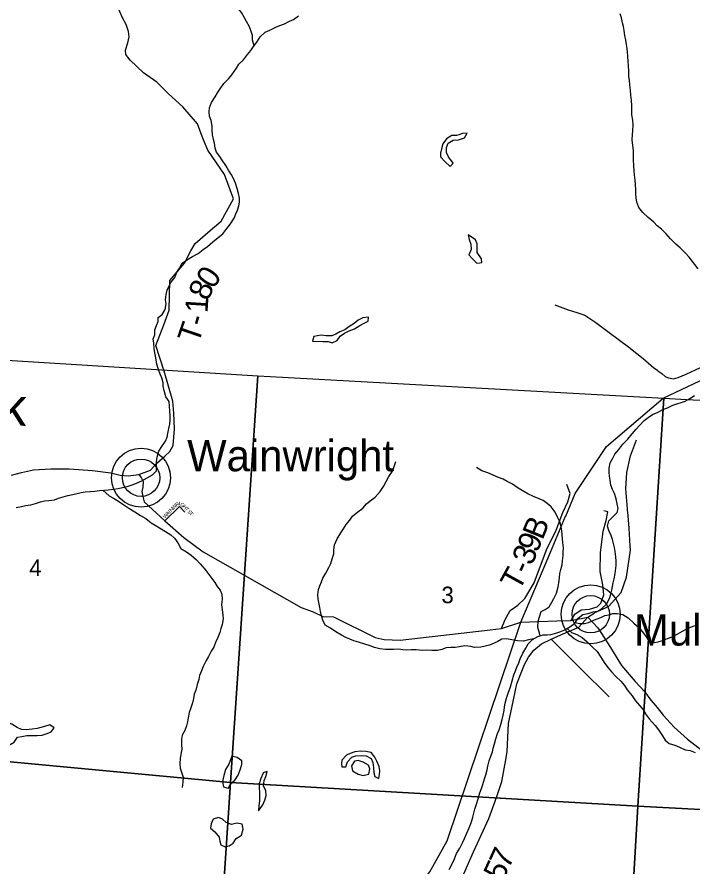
# Model space of a CAD drawing. Extents: x 1715311 to 2083412, y 146837 to 553079.
# Drawn here: x 1969763 to 1978768, y 403543 to 414870 of the extents above; entities that cross this region are included whole.
import ezdxf

# ---------------------------------------------------------------- set-up
doc = ezdxf.new("R2010")
doc.units = 0
for name, color, linetype in [('GM_X_County_Road', 7, 'Continuous'), ('GM_X_Major_River_Text', 7, 'Continuous'), ('GM_X_Minor_Lake', 7, 'Continuous'), ('GM_X_Minor_River', 7, 'Continuous'), ('GM_X_Section', 7, 'Continuous'), ('GM_X_Section_Text', 7, 'Continuous'), ('GM_X_State_Route', 7, 'Continuous'), ('GM_X_Township_Road', 7, 'Continuous'), ('GM_X_Township_Road_Text', 7, 'Continuous'), ('GM_X_Township_ROW', 7, 'Continuous'), ('GM_X_Township_Subdivision', 7, 'Continuous'), ('GM_X_Township_Subdivision_Text', 7, 'Continuous'), ('GM_X_Unincorporated', 7, 'Continuous'), ('GM_X_Unincorporated_Location', 7, 'Continuous'), ('GM_X_Unincorporated_Text', 7, 'Continuous')]:
    doc.layers.add(name, color=color, linetype=linetype)

msp = doc.modelspace()

# ---------------------------------------------------------------- linework, layer by layer
at = {"layer": 'GM_X_County_Road'}
for points in [[(1969690, 408766), (1969822, 408801), (1969984, 408834), (1970214, 408850), (1970458, 408849), (1970769, 408826), (1971014, 408794), (1971138, 408763), (1971244, 408756), (1971384, 408773), (1971419, 408733), (1971445, 408681), (1971440, 408605), (1971426, 408547), (1971437, 408481), (1971455, 408409), (1971733, 408154), (1971984, 407934), (1972245, 407742), (1973547, 407002), (1973710, 406945), (1973836, 406881), (1973977, 406876), (1974536, 406600), (1974656, 406575), (1974868, 406567), (1976068, 406704)], [(1976068, 406704), (1976215, 406720), (1976476, 406805), (1976952, 406822), (1976954, 406822)], [(1976954, 406822), (1977145, 406829), (1977161, 406830), (1977367, 406873), (1977498, 406731), (1977669, 406468), (1977817, 406228), (1977999, 406015), (1978120, 405880), (1978208, 405767), (1978209, 405766)], [(1978209, 405766), (1978211, 405763), (1978292, 405668), (1978369, 405568), (1978518, 405404), (1978696, 405247), (1978891, 405095), (1979079, 404890), (1979255, 404702), (1979433, 404391), (1979537, 404242), (1979659, 403933), (1979721, 403720), (1979743, 403581), (1979744, 403576)]]:
    msp.add_lwpolyline(points, dxfattribs=at)
at = {"layer": 'GM_X_Minor_Lake'}
for points in [[(1975647, 413301), (1975616, 413289), (1975556, 413291), (1975486, 413247), (1975436, 413179), (1975416, 413113), (1975404, 413055), (1975404, 413005), (1975462, 412943), (1975534, 412879)], [(1975534, 412879), (1975571, 412924), (1975510, 413007), (1975484, 413065), (1975486, 413133), (1975506, 413187), (1975572, 413227), (1975646, 413233), (1975722, 413261), (1975760, 413323), (1975696, 413319), (1975647, 413301)], [(1975772, 411969), (1975784, 411905), (1975808, 411843), (1975812, 411774), (1975780, 411702), (1975830, 411646), (1975887, 411588), (1975927, 411594)], [(1975927, 411594), (1975953, 411598), (1975951, 411648), (1975891, 411730), (1975891, 411849), (1975869, 411899), (1975772, 411969)], [(1974414, 410805), (1974439, 410816), (1974445, 410868), (1974371, 410862), (1974307, 410828), (1974255, 410786), (1974183, 410740), (1974131, 410702), (1974062, 410674), (1974010, 410642), (1973958, 410622), (1973880, 410622), (1973816, 410630), (1973718, 410614)], [(1973718, 410614), (1973698, 410552), (1973838, 410544), (1973908, 410546), (1973960, 410530), (1974028, 410560), (1974066, 410616), (1974127, 410656), (1974189, 410686), (1974259, 410714), (1974331, 410758), (1974387, 410792), (1974414, 410805)], [(1969295, 405416), (1969269, 405344), (1969233, 405288), (1969264, 405236), (1969330, 405258), (1969397, 405288), (1969452, 405281), (1969530, 405215), (1969582, 405177), (1969674, 405173), (1969726, 405205), (1969768, 405273), (1969828, 405280), (1969894, 405294), (1969956, 405294), (1970030, 405296), (1970096, 405298), (1970167, 405323)], [(1970167, 405323), (1970220, 405343), (1970260, 405399), (1970199, 405439), (1970131, 405416), (1970080, 405400), (1970030, 405390), (1969963, 405380), (1969885, 405370), (1969823, 405374), (1969765, 405403), (1969695, 405447), (1969625, 405473), (1969555, 405461), (1969479, 405426), (1969417, 405408), (1969365, 405416), (1969295, 405416)], [(1974565, 404730), (1974582, 404722), (1974592, 404774), (1974594, 404824), (1974588, 404884), (1974558, 404954), (1974529, 405008), (1974479, 405067), (1974411, 405083), (1974337, 405087), (1974265, 405077), (1974201, 405057), (1974151, 405034), (1974091, 404968), (1974085, 404918)], [(1972626, 405018), (1972583, 404914), (1972539, 404842), (1972519, 404764), (1972499, 404682), (1972513, 404612), (1972560, 404598)], [(1972560, 404598), (1972580, 404592), (1972609, 404650), (1972663, 404700), (1972709, 404766), (1972737, 404838), (1972757, 404908), (1972756, 404958), (1972694, 405004), (1972626, 405018)], [(1974085, 404918), (1974088, 404878), (1974142, 404879), (1974165, 404945), (1974221, 405005), (1974277, 405023), (1974357, 405029), (1974415, 405023), (1974479, 404987), (1974502, 404934), (1974512, 404864), (1974516, 404798), (1974528, 404748), (1974565, 404730)], [(1974426, 404777), (1974448, 404782), (1974464, 404851), (1974444, 404901), (1974373, 404941), (1974309, 404963), (1974259, 404951)], [(1974259, 404951), (1974218, 404889), (1974234, 404825), (1974306, 404781), (1974376, 404763), (1974426, 404777)], [(1972979, 404290), (1973039, 404372), (1973064, 404434), (1973084, 404494), (1973076, 404558), (1973046, 404626), (1973057, 404696), (1973079, 404750), (1973097, 404814), (1973057, 404800)], [(1973057, 404800), (1973043, 404795), (1973013, 404721), (1972988, 404651), (1972988, 404601), (1972992, 404529), (1972992, 404474), (1972992, 404424), (1972983, 404360), (1972979, 404290)], [(1972375, 404182), (1972351, 404116), (1972341, 404060), (1972397, 404010), (1972456, 403942), (1972466, 403888), (1972480, 403837), (1972534, 403813), (1972590, 403825), (1972642, 403861), (1972682, 403921), (1972727, 403950)], [(1972727, 403950), (1972754, 403969), (1972777, 404049), (1972763, 404115), (1972693, 404125), (1972621, 404111), (1972551, 404137), (1972499, 404178), (1972445, 404202), (1972375, 404182)]]:
    msp.add_lwpolyline(points, dxfattribs=at)
at = {"layer": 'GM_X_Minor_River'}
for points in [[(1972921, 414488), (1972902, 414561), (1972900, 414625), (1972880, 414691), (1972860, 414741), (1972820, 414811), (1972792, 414861), (1972752, 414929), (1972714, 414981), (1972680, 415031), (1972640, 415081), (1972594, 415159), (1972552, 415231), (1972498, 415295), (1972441, 415339), (1972393, 415369)], [(1971788, 409745), (1971745, 409809), (1971723, 409891), (1971711, 409947), (1971709, 409997), (1971693, 410061), (1971671, 410112), (1971649, 410174), (1971627, 410244), (1971611, 410330), (1971601, 410396), (1971591, 410452), (1971585, 410522), (1971577, 410582), (1971597, 410636), (1971599, 410702), (1971619, 410760), (1971643, 410812), (1971645, 410864), (1971697, 410906), (1971737, 410974), (1971749, 411048), (1971743, 411102), (1971751, 411174), (1971762, 411228), (1971786, 411280), (1971814, 411330), (1971864, 411400), (1971892, 411468), (1971926, 411522), (1971964, 411588), (1972032, 411640), (1972102, 411680), (1972176, 411720), (1972243, 411770), (1972301, 411814), (1972371, 411876), (1972443, 411932), (1972505, 411982), (1972543, 412032), (1972607, 412112), (1972654, 412190), (1972680, 412246), (1972700, 412296), (1972716, 412354), (1972726, 412404), (1972726, 412458), (1972714, 412516), (1972694, 412584), (1972672, 412654), (1972646, 412716), (1972622, 412769), (1972581, 412829), (1972543, 412893), (1972497, 412961), (1972465, 413011), (1972421, 413069), (1972403, 413121), (1972393, 413187), (1972381, 413237), (1972367, 413301), (1972363, 413365), (1972363, 413415), (1972351, 413489), (1972329, 413547), (1972321, 413605), (1972327, 413661), (1972355, 413731), (1972401, 413807), (1972433, 413859), (1972469, 413913), (1972517, 413983), (1972584, 414051), (1972626, 414101), (1972688, 414189), (1972716, 414241), (1972782, 414301), (1972834, 414371), (1972880, 414425), (1972912, 414475), (1972956, 414537), (1973001, 414607), (1973069, 414669), (1973131, 414697), (1973211, 414735), (1973265, 414755), (1973325, 414779), (1973395, 414813), (1973448, 414839), (1973514, 414887)], [(1978837, 411515), (1978717, 411671), (1978667, 411723), (1978596, 411793), (1978540, 411841), (1978468, 411913), (1978404, 411983), (1978348, 412045), (1978290, 412087), (1978246, 412137), (1978170, 412199), (1978101, 412263), (1978047, 412333), (1978021, 412403), (1978009, 412459), (1978005, 412511), (1978005, 412567), (1978003, 412637), (1977997, 412697), (1977989, 412767), (1977983, 412819), (1977979, 412887), (1977977, 412969), (1977973, 413023), (1977973, 413091), (1977965, 413159), (1977959, 413233), (1977961, 413303), (1977965, 413353), (1977971, 413433), (1977967, 413497), (1977955, 413565), (1977955, 413691), (1977949, 413759), (1977941, 413829), (1977933, 413897), (1977925, 413967), (1977921, 414027), (1977915, 414079), (1977911, 414146), (1977907, 414222), (1977905, 414278), (1977901, 414348), (1977895, 414402), (1977891, 414452), (1977881, 414506), (1977871, 414562), (1977861, 414624), (1977853, 414692), (1977843, 414742), (1977829, 414792), (1977815, 414860), (1977799, 414912)], [(1969754, 408333), (1969822, 408347), (1969876, 408361), (1969946, 408371), (1970008, 408386), (1970078, 408408), (1970128, 408422), (1970186, 408428), (1970262, 408438), (1970314, 408456), (1970378, 408477), (1970440, 408493), (1970508, 408507), (1970564, 408521), (1970616, 408533), (1970672, 408541), (1970738, 408548), (1970800, 408552), (1970862, 408560), (1970924, 408566), (1970978, 408568), (1971042, 408578), (1971110, 408587), (1971168, 408599), (1971230, 408615), (1971296, 408637), (1971356, 408659), (1971428, 408691), (1971498, 408730), (1971566, 408770), (1971622, 408822), (1971621, 408890), (1971619, 408940), (1971629, 409006), (1971653, 409084), (1971693, 409146), (1971740, 409216), (1971764, 409270), (1971770, 409320), (1971786, 409388), (1971800, 409444), (1971802, 409494), (1971803, 409550), (1971799, 409622), (1971788, 409745)], [(1976423, 406208), (1976447, 406262), (1976466, 406318), (1976502, 406394), (1976542, 406460), (1976572, 406518), (1976630, 406574), (1976700, 406615), (1976772, 406637), (1976824, 406635), (1976876, 406639), (1976942, 406657), (1976994, 406677), (1977062, 406702), (1977125, 406744), (1977193, 406792), (1977239, 406860), (1977301, 406906), (1977371, 406920), (1977437, 406942), (1977499, 406953), (1977553, 406989), (1977615, 407045), (1977657, 407123), (1977674, 407177), (1977686, 407231), (1977694, 407281), (1977704, 407331), (1977716, 407381), (1977730, 407453), (1977743, 407561), (1977743, 407619), (1977741, 407675), (1977729, 407749), (1977722, 407800), (1977710, 407854), (1977696, 407906), (1977678, 407960), (1977648, 408026), (1977631, 408086), (1977645, 408158), (1977705, 408212), (1977759, 408268), (1977771, 408320), (1977757, 408384), (1977746, 408450), (1977724, 408518), (1977694, 408574), (1977674, 408630), (1977664, 408696), (1977655, 408751), (1977649, 408805), (1977651, 408859), (1977665, 408927), (1977699, 408991), (1977725, 409043), (1977778, 409106), (1977834, 409178), (1977898, 409244), (1977956, 409314), (1978010, 409376), (1978053, 409428), (1978117, 409494), (1978187, 409546), (1978237, 409578), (1978295, 409601), (1978367, 409641), (1978429, 409663), (1978497, 409699), (1978664, 409750)], [(1978664, 409750), (1978724, 409788), (1978789, 409826)], [(1976644, 406582), (1976578, 406572), (1976510, 406554), (1976432, 406558), (1976356, 406572), (1976285, 406585), (1976221, 406579), (1976169, 406549), (1976118, 406525), (1976058, 406499), (1976000, 406485), (1975940, 406474), (1975858, 406470), (1975807, 406482), (1975729, 406490), (1975659, 406476), (1975601, 406469), (1975543, 406469), (1975479, 406463), (1975423, 406441), (1975363, 406429), (1975291, 406427), (1975217, 406432), (1975161, 406428), (1975081, 406436), (1975017, 406436), (1974957, 406434), (1974901, 406439), (1974849, 406447), (1974777, 406443), (1974723, 406441), (1974671, 406443), (1974597, 406451), (1974527, 406470), (1974467, 406490), (1974397, 406512), (1974312, 406540), (1974252, 406555), (1974196, 406577), (1974144, 406601), (1974084, 406633), (1974008, 406675), (1973938, 406724), (1973867, 406766), (1973835, 406830), (1973821, 406888), (1973807, 406948), (1973795, 407002), (1973782, 407066), (1973774, 407116), (1973772, 407170), (1973780, 407239), (1973796, 407291), (1973818, 407342), (1973835, 407394), (1973877, 407460), (1973917, 407532), (1973943, 407586), (1973963, 407650), (1973982, 407714), (1973982, 407768), (1973994, 407838), (1974026, 407918), (1974078, 407996), (1974110, 408048), (1974147, 408108), (1974195, 408164), (1974233, 408216), (1974301, 408278), (1974371, 408324), (1974417, 408384), (1974467, 408422), (1974534, 408473), (1974602, 408545), (1974646, 408613), (1974680, 408679), (1974718, 408747), (1974765, 408819), (1974785, 408881), (1974811, 408947)], [(1976731, 406625), (1976721, 406661), (1976701, 406736), (1976705, 406820), (1976721, 406876), (1976745, 406946), (1976797, 406974), (1976852, 407011), (1976886, 407071), (1976914, 407123), (1976950, 407193), (1976970, 407275), (1976981, 407329), (1976989, 407395), (1976993, 407455), (1977007, 407507), (1977023, 407569), (1977031, 407623), (1977038, 407693), (1977040, 407743), (1977042, 407795), (1977036, 407866), (1977028, 407916), (1977025, 407972), (1977021, 408022), (1977011, 408074), (1976995, 408142), (1976969, 408194), (1976930, 408270), (1976878, 408342), (1976826, 408385), (1976772, 408425), (1976720, 408451), (1976644, 408481), (1976567, 408517), (1976491, 408560), (1976439, 408592), (1976363, 408646), (1976293, 408682), (1976241, 408709), (1976175, 408733), (1976106, 408765), (1976034, 408797), (1975956, 408824), (1975884, 408866)], [(1970906, 408564), (1970990, 408490), (1971050, 408460), (1971115, 408419), (1971187, 408369), (1971253, 408323), (1971333, 408277), (1971409, 408228), (1971478, 408186), (1971552, 408130), (1971604, 408098), (1971662, 408063), (1971742, 408015), (1971810, 407969), (1971861, 407927), (1971905, 407861), (1971945, 407788), (1972021, 407744), (1972083, 407700), (1972154, 407636), (1972202, 407585), (1972266, 407511), (1972320, 407441), (1972359, 407389), (1972399, 407335), (1972431, 407282), (1972469, 407230), (1972491, 407180), (1972498, 407114), (1972488, 407040), (1972494, 406970), (1972506, 406904), (1972508, 406852), (1972497, 406774), (1972479, 406722), (1972463, 406670), (1972439, 406600), (1972407, 406534), (1972385, 406472), (1972348, 406420), (1972314, 406346), (1972282, 406294), (1972244, 406216), (1972220, 406158), (1972195, 406096), (1972183, 406040), (1972165, 405974), (1972143, 405900), (1972125, 405846), (1972113, 405790), (1972100, 405730), (1972078, 405664), (1972058, 405602), (1972042, 405532), (1972034, 405476), (1972021, 405422), (1971997, 405364), (1971965, 405300), (1971955, 405246), (1971955, 405176), (1971958, 405114), (1971946, 405048), (1971936, 404990), (1971930, 404924), (1971936, 404858), (1971959, 404792), (1971975, 404740), (1971973, 404672), (1971965, 404600)], [(1977197, 406799), (1977257, 406788), (1977323, 406786), (1977377, 406802), (1977477, 406845), (1977539, 406869), (1977595, 406895), (1977645, 406905), (1977699, 406919), (1977757, 406921), (1977835, 406908), (1977906, 406864), (1977980, 406794), (1978046, 406734), (1978090, 406682), (1978134, 406623), (1978175, 406561), (1978253, 406535), (1978305, 406543), (1978361, 406563), (1978427, 406588), (1978491, 406612), (1978565, 406652), (1978627, 406684), (1978678, 406714), (1978738, 406740), (1978790, 406760)], [(1977090, 406721), (1977150, 406670), (1977222, 406642), (1977290, 406600), (1977356, 406544), (1977430, 406471), (1977491, 406413), (1977541, 406341), (1977595, 406255), (1977637, 406198), (1977680, 406144), (1977742, 406080), (1977806, 406020), (1977856, 405960), (1977891, 405905), (1977957, 405825), (1978001, 405759), (1978059, 405689), (1978114, 405627), (1978144, 405570), (1978182, 405516), (1978264, 405428), (1978310, 405370), (1978361, 405292), (1978397, 405235), (1978451, 405189), (1978525, 405165), (1978589, 405139), (1978664, 405106), (1978732, 405094), (1978798, 405070)], [(1975519, 403508), (1975557, 403578), (1975590, 403650), (1975618, 403722), (1975660, 403794), (1975698, 403864), (1975726, 403924), (1975757, 403992), (1975787, 404064), (1975817, 404146), (1975835, 404208), (1975849, 404262), (1975862, 404312), (1975882, 404378), (1975906, 404452), (1975930, 404530), (1975950, 404588), (1975969, 404644), (1975991, 404716), (1976007, 404770), (1976025, 404838), (1976033, 404888), (1976052, 404956), (1976076, 405018), (1976096, 405076), (1976108, 405126), (1976124, 405186), (1976140, 405250), (1976165, 405320), (1976185, 405372), (1976207, 405440), (1976225, 405510), (1976241, 405568), (1976254, 405628), (1976256, 405678), (1976266, 405728), (1976282, 405794), (1976306, 405858), (1976335, 405944), (1976359, 406022), (1976379, 406102), (1976405, 406156), (1976423, 406208)]]:
    msp.add_lwpolyline(points, dxfattribs=at)
at = {"layer": 'GM_X_Section'}
for points in [[(1967776, 410413), (1972971, 410089), (1972606, 404667), (1967021, 405193), (1967438, 410443)], [(1972971, 410089), (1973301, 410069), (1978378, 409789), (1978033, 404353), (1972606, 404667)], [(1978681, 409772), (1983928, 409514), (1983542, 404061), (1978033, 404353), (1978378, 409789)], [(1967021, 405193), (1972606, 404667), (1972254, 399358), (1966614, 399911)], [(1978033, 404353), (1977725, 399082), (1972254, 399358), (1972606, 404667)], [(1978033, 404353), (1983542, 404061), (1983136, 398808), (1977725, 399082)]]:
    msp.add_lwpolyline(points, close=True, dxfattribs=at)
at = {"layer": 'GM_X_State_Route'}
for points in [[(1977071, 408219), (1977072, 408220), (1977198, 408518), (1977615, 409145), (1978371, 409789), (1978943, 410061), (1979249, 410206), (1979764, 410451), (1980253, 410677), (1980641, 410858), (1980964, 411010), (1981159, 411070), (1981479, 411139), (1982025, 411215), (1982669, 411304), (1983500, 411419), (1983716, 411449), (1985732, 411720), (1986009, 411733), (1987799, 411756), (1989364, 411757), (1989611, 411701)], [(1967835, 398036), (1968254, 398099), (1968975, 398269), (1969638, 398455), (1970078, 398638), (1970229, 398706), (1970562, 398854), (1971089, 399205), (1971558, 399550), (1972330, 400277), (1973608, 401620), (1975103, 403268), (1975262, 403479), (1975493, 403891), (1976476, 406805), (1976846, 407687), (1977071, 408219)]]:
    msp.add_lwpolyline(points, dxfattribs=at)
at = {"layer": 'GM_X_Township_Road'}
for points in [[(1971238, 414337), (1971213, 414369), (1971207, 414430), (1971241, 414525), (1971259, 414604), (1971248, 414679), (1971218, 414771), (1971169, 414859), (1971104, 415003), (1971066, 415100), (1970982, 415190), (1970814, 415328), (1970665, 415473)], [(1972247, 413233), (1972229, 413278), (1972169, 413447), (1971971, 413673), (1971782, 413848), (1971625, 414002), (1971446, 414128), (1971269, 414297), (1971238, 414337)], [(1971384, 408773), (1971540, 408830), (1971625, 408924), (1971733, 409017), (1971800, 409080), (1971844, 409158), (1971860, 409380), (1971852, 409590), (1971841, 409749), (1971723, 410150), (1971614, 410491), (1971717, 410768), (1971788, 410963), (1971797, 411359), (1971996, 411591), (1972080, 411753), (1972136, 411852), (1972305, 411998), (1972482, 412151), (1972645, 412447), (1972527, 412772), (1972304, 413096), (1972247, 413233)], [(1977925, 410463), (1977937, 410454), (1978105, 410320), (1978247, 410197), (1978294, 410162)], [(1978421, 410069), (1978429, 410066), (1978442, 410060), (1978507, 410047), (1978572, 410067), (1978676, 410112), (1979059, 410288), (1979105, 410320), (1979137, 410320), (1979189, 410307), (1979208, 410275), (1979249, 410206)], [(1978294, 410162), (1978301, 410156), (1978351, 410119), (1978397, 410080), (1978421, 410069)], [(1977895, 408314), (1977874, 408582), (1977887, 408798), (1977933, 409021), (1978017, 409237)], [(1976215, 406720), (1976266, 406841), (1976333, 406962), (1976433, 407030), (1976526, 407119), (1976653, 407330), (1976817, 407769), (1976943, 408032), (1977036, 408268), (1977101, 408407), (1977130, 408521), (1977085, 408638)], [(1977145, 406829), (1977193, 406914), (1977280, 406969), (1977388, 406978), (1977490, 407009), (1977540, 407057), (1977579, 407169), (1977566, 407305), (1977533, 407479), (1977535, 407730), (1977570, 408020), (1977611, 408161), (1977634, 408277), (1977580, 408290)], [(1977932, 407818), (1977919, 408059), (1977898, 408278), (1977897, 408283), (1977895, 408314)], [(1977451, 406927), (1977461, 406934), (1977642, 407016), (1977811, 407201), (1977880, 407405), (1977934, 407763), (1977935, 407769), (1977932, 407818)], [(1976524, 406241), (1976578, 406338), (1976646, 406431), (1976749, 406517), (1976880, 406577), (1977007, 406635), (1977246, 406741), (1977367, 406873), (1977451, 406927)], [(1976880, 406577), (1977265, 406193), (1977265, 406193)], [(1976273, 404973), (1976292, 405083), (1976311, 405457), (1976376, 405771), (1976419, 405983), (1976486, 406151), (1976513, 406220), (1976524, 406241)], [(1975714, 403452), (1975842, 403744), (1976050, 404188), (1976114, 404371), (1976154, 404482), (1976221, 404680), (1976273, 404973)]]:
    msp.add_lwpolyline(points, dxfattribs=at)
at = {"layer": 'GM_X_Township_ROW'}
for points in [[(1976927, 411034), (1977105, 410970), (1977222, 410931), (1977325, 410898), (1977475, 410801), (1977650, 410664), (1977925, 410463)], [(1977265, 406193), (1977651, 405810)]]:
    msp.add_lwpolyline(points, dxfattribs=at)
at = {"layer": 'GM_X_Township_Subdivision'}
msp.add_lwpolyline([(1971733, 408154), (1971926, 408349), (1971997, 408270)], dxfattribs=at)
at = {"layer": 'GM_X_Unincorporated'}
for centre, radius in [((1971416, 408730), 393), ((1971416, 408730), 249), ((1977405, 406911), 393), ((1977405, 406911), 249)]:
    msp.add_circle(centre, radius, dxfattribs=at)
at = {"layer": 'GM_X_Unincorporated_Location'}
for p, q in [((1971416, 408730), (1971416, 408730)), ((1977405, 406911), (1977405, 406911))]:
    msp.add_line(p, q, dxfattribs=at)

# ---------------------------------------------------------------- texts
at = {"layer": 'GM_X_Major_River_Text'}
msp.add_text('Creek', height=500, rotation=357.9981, dxfattribs=at).set_placement((1968099, 409483))
at = {"layer": 'GM_X_Section_Text'}
for s, p in [('4', (1969926, 407420)), ('3', (1975417, 407058))]:
    msp.add_text(s, height=221, rotation=0, dxfattribs=at).set_placement(p)
at = {"layer": 'GM_X_Township_Road_Text'}
for s, rotation, p in [('0', 56.3936, (1972377, 411232)), ('8', 65.0409, (1972304, 411075)), ('1', 86.3495, (1972300, 410919)), ('-', 74.5849, (1972256, 410734)), ('T', 71.1205, (1972178, 410503)), ('B', 67.8251, (1976763, 407889)), ('9', 67.6247, (1976692, 407718)), ('3', 67.4471, (1976622, 407548)), ('-', 66.1338, (1976569, 407429)), ('T', 61.2208, (1976449, 407208)), ('7', 65.3196, (1976313, 403506)), ('5', 65.2872, (1976235, 403338))]:
    msp.add_text(s, height=300, rotation=rotation, dxfattribs=at).set_placement(p)
at = {"layer": 'GM_X_Township_Subdivision_Text'}
for s, rotation, p in [('W', 45.6607, (1971851, 408304)), ('R', 30.1581, (1971889, 408342)), ('I', 359.1529, (1971916, 408361)), ('G', 328.1477, (1971931, 408362)), ('H', 312.6451, (1971966, 408341)), ('W', 45.6607, (1971735, 408184)), ('A', 45.6607, (1971775, 408225)), ('I', 45.6607, (1971805, 408256)), ('N', 45.6607, (1971821, 408272)), ('T', 312.6451, (1971996, 408309)), ('S', 312.6451, (1972029, 408273)), ('T', 312.6451, (1972052, 408247))]:
    msp.add_text(s, height=50, rotation=rotation, dxfattribs=at).set_placement(p)
at = {"layer": 'GM_X_Unincorporated_Text'}
for s, p in [('Wainwright', (1972029, 408817)), ('Mulga', (1977982, 406494))]:
    msp.add_text(s, height=417, rotation=0, dxfattribs=at).set_placement(p)

doc.saveas('drawing.dxf')
